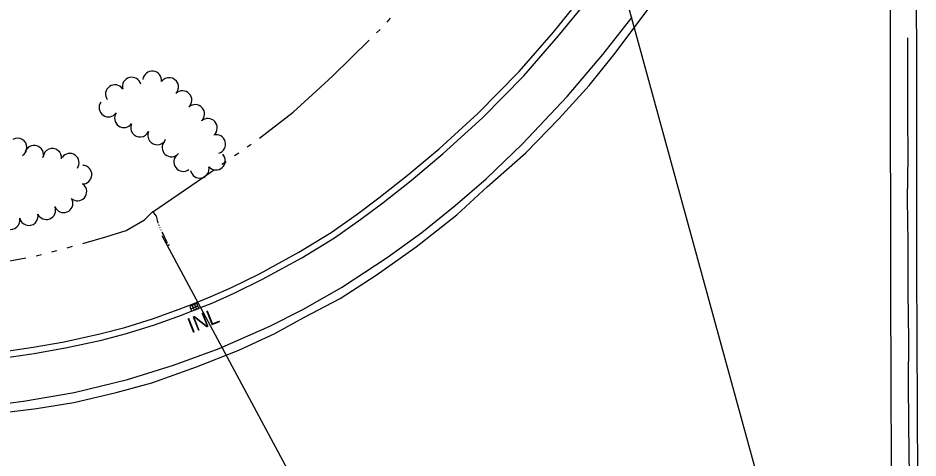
# Model space of a CAD drawing. Extents: x 589250 to 1188077, y 162953 to 363065.
# Drawn here: x 593646.2 to 594001.4, y 174071.1 to 174244.8 of the extents above; entities that cross this region are included whole.
import ezdxf

# ---------------------------------------------------------------- set-up
doc = ezdxf.new("R2010")
doc.units = 0
for name, color, linetype in [('E_DRN', 7, 'Continuous'), ('E_DRN_Pipe', 7, 'Continuous'), ('E_DRN_SS_UG', 7, 'Continuous'), ('E_DRN_Text', 7, 'Continuous'), ('E_LAND_TreeLine_P', 7, 'Continuous'), ('E_RDWY', 7, 'Continuous'), ('E_RDWY_C_and_G', 7, 'Continuous'), ('E_RDWY_Gravel', 7, 'Continuous'), ('E_WTR_FlowLine', 7, 'Continuous')]:
    doc.layers.add(name, color=color, linetype=linetype)

msp = doc.modelspace()

# ---------------------------------------------------------------- linework, layer by layer
at = {"layer": 'E_DRN'}
for p, q in [((593716.8, 174132.02), (593714.01, 174130.92)), ((593714.01, 174130.92), (593714.75, 174129.06)), ((593714.38, 174129.99), (593717.17, 174131.1)), ((593714.75, 174129.06), (593717.54, 174130.17)), ((593714.94, 174131.29), (593715.68, 174129.43)), ((593715.87, 174131.66), (593716.61, 174129.8)), ((593717.54, 174130.17), (593716.8, 174132.02))]:
    msp.add_line(p, q, dxfattribs=at)
msp.add_arc((593705.32, 174155.67), 0.688, 244.4487, 350.7089, dxfattribs=at)
at = {"layer": 'E_DRN_Pipe'}
msp.add_lwpolyline([(593997.26, 174236.88), (593997.22, 174205.91), (593997.45, 174190.1), (593997.17, 174173.15), (593997.38, 174156.28), (593997.4, 174136.85), (593997.6, 174117.51), (593997.58, 174100.98), (593997.68, 174084.29), (593997.91, 174063.67), (593997.8, 174044.52), (593998.12, 174021.41), (593998.36, 173997.81), (593998.8, 173968.11)], dxfattribs=at)
at = {"layer": 'E_DRN_SS_UG'}
for p, q in [((593862.64, 174338.2), (593948.9, 174023.91)), ((593702.98, 174158.95), (593820.56, 173940.11))]:
    msp.add_line(p, q, dxfattribs=at)
at = {"layer": 'E_LAND_TreeLine_P'}
for centre, radius, start, end in [((593699.2, 174220.11), 3.7, 353.8888, 173.8888), ((593684.46, 174214.69), 3.7, 35.7089, 215.7089), ((593691.12, 174217.65), 3.7, 15.05, 195.05), ((593705.87, 174217.52), 3.7, 324.1439, 144.1439), ((593711.12, 174212.31), 3.7, 313.7232, 133.7232), ((593681.91, 174209.42), 3.7, 145.4761, 325.4761), ((593716.14, 174206.87), 3.7, 312.3616, 132.3616), ((593688.02, 174205.22), 3.7, 145.4761, 325.4761), ((593721.14, 174201.39), 3.7, 312.3616, 132.3616), ((593694.38, 174201.48), 3.7, 155.5504, 335.5504), ((593646.08, 174193.61), 3.67, 300.2626, 120.2626), ((593701.12, 174198.42), 3.7, 155.5504, 335.5504), ((593724.46, 174195), 3.7, 285.7573, 105.7573), ((593652.57, 174190.77), 3.67, 342.5788, 162.5788), ((593706.79, 174193.69), 3.7, 138.5033, 318.5033), ((593659.79, 174189.57), 3.67, 353.1605, 173.1605), ((593666.66, 174187.64), 3.67, 324.6294, 144.6294), ((593711.41, 174187.93), 3.7, 127.0412, 307.0412), ((593724.32, 174188.48), 3.7, 222.6473, 42.6473), ((593671.68, 174182.92), 3.67, 267.4374, 87.4374), ((593717.95, 174185.27), 3.7, 191.3186, 11.3186), ((593669.68, 174176.28), 3.67, 227.8614, 47.8614), ((593664.22, 174171.61), 3.67, 201.7393, 21.7393), ((593657.4, 174168.89), 3.67, 201.7393, 21.7393), ((593643.29, 174165), 3.67, 192.3237, 12.3237), ((593650.46, 174166.56), 3.67, 192.3237, 12.3237)]:
    msp.add_arc(centre, radius, start, end, dxfattribs=at)
at = {"layer": 'E_RDWY'}
for p, q in [((594000.92, 174228.15), (594000.77, 174260.2)), ((593877.05, 174230.32), (593888.61, 174245.1)), ((593862.96, 174213.71), (593877.05, 174230.32)), ((594000.95, 174202.45), (594000.92, 174228.15)), ((593845.36, 174195.08), (593862.96, 174213.71)), ((594000.93, 174171.67), (594000.95, 174202.45)), ((593831.02, 174181.23), (593845.36, 174195.08)), ((593818.79, 174170.77), (593831.02, 174181.23)), ((593805.59, 174160.09), (593818.79, 174170.77)), ((594000.93, 174171.67), (594000.93, 174171.67)), ((594000.96, 174145.69), (594000.93, 174171.67)), ((593791.97, 174150.2), (593805.59, 174160.09)), ((593773.85, 174138.45), (593791.97, 174150.2)), ((594001.02, 174118.58), (594000.96, 174145.69)), ((593758.64, 174129.71), (593773.85, 174138.45)), ((593745.55, 174123.17), (593758.64, 174129.71)), ((593725.61, 174114.34), (593745.55, 174123.17)), ((594001.23, 174090.48), (594001.02, 174118.58)), ((593707.6, 174107.72), (593725.61, 174114.34)), ((593689.38, 174102.08), (593707.6, 174107.72)), ((593668.39, 174096.98), (593689.38, 174102.08)), ((593648.35, 174093.47), (593668.39, 174096.98)), ((593632.23, 174091.41), (593648.35, 174093.47)), ((594001.4, 174057.16), (594001.23, 174090.48))]:
    msp.add_line(p, q, dxfattribs=at)
at = {"layer": 'E_RDWY_C_and_G'}
for p, q in [((593857.54, 174239.14), (593869.07, 174253.43)), ((593859.45, 174237.53), (593871.05, 174251.9)), ((593843.98, 174223.66), (593857.54, 174239.14)), ((593845.81, 174221.96), (593859.45, 174237.53)), ((593827.75, 174207.1), (593843.98, 174223.66)), ((593829.48, 174205.3), (593845.81, 174221.96)), ((593812.37, 174193.13), (593827.75, 174207.1)), ((593814.02, 174191.24), (593829.48, 174205.3)), ((593799.75, 174182.53), (593812.37, 174193.13)), ((593801.33, 174180.59), (593814.02, 174191.24)), ((593788.64, 174173.75), (593799.75, 174182.53)), ((593790.16, 174171.77), (593801.33, 174180.59)), ((593780.04, 174167.33), (593788.64, 174173.75)), ((593781.51, 174165.3), (593790.16, 174171.77)), ((593769.8, 174160.1), (593780.04, 174167.33)), ((593771.17, 174158.01), (593781.51, 174165.3)), ((593757, 174152.32), (593769.8, 174160.1)), ((593758.25, 174150.15), (593771.17, 174158.01)), ((593741.52, 174143.85), (593757, 174152.32)), ((593742.68, 174141.63), (593758.25, 174150.15)), ((593730.48, 174138.4), (593741.52, 174143.85)), ((593731.54, 174136.14), (593742.68, 174141.63)), ((593722.09, 174134.67), (593730.48, 174138.4)), ((593715.35, 174131.99), (593722.09, 174134.67)), ((593723.06, 174132.36), (593731.54, 174136.14)), ((593699.32, 174126.07), (593709.88, 174129.84)), ((593709.88, 174129.84), (593715.35, 174131.99)), ((593710.76, 174127.5), (593716.27, 174129.66)), ((593716.27, 174129.66), (593723.06, 174132.36)), ((593688.37, 174122.67), (593699.32, 174126.07)), ((593700.11, 174123.69), (593710.76, 174127.5)), ((593678.55, 174120.06), (593688.37, 174122.67)), ((593689.06, 174120.27), (593700.11, 174123.69)), ((593664.39, 174117), (593678.55, 174120.06)), ((593679.14, 174117.63), (593689.06, 174120.27)), ((593652.26, 174114.85), (593664.39, 174117)), ((593664.92, 174114.55), (593679.14, 174117.63)), ((593635.39, 174112.42), (593652.26, 174114.85)), ((593635.64, 174109.93), (593652.65, 174112.39)), ((593652.65, 174112.39), (593664.82, 174114.53))]:
    msp.add_line(p, q, dxfattribs=at)
at = {"layer": 'E_RDWY_Gravel'}
for p, q in [((593990.44, 174268.25), (593990.36, 174238.32)), ((593881.37, 174230.28), (593894.9, 174248.23)), ((593990.36, 174238.32), (593990.47, 174197.6)), ((593871.61, 174218.1), (593881.37, 174230.28)), ((593859.83, 174205.06), (593871.61, 174218.1)), ((593846.63, 174191.59), (593859.83, 174205.06)), ((593990.47, 174197.6), (593990.56, 174169.51)), ((593831.39, 174178.09), (593846.63, 174191.59)), ((593819.37, 174167.09), (593831.39, 174178.09)), ((593990.56, 174169.51), (593990.58, 174133.67)), ((593803.31, 174154.38), (593819.37, 174167.09)), ((593787.62, 174143.31), (593803.31, 174154.38)), ((593773.33, 174134.1), (593787.62, 174143.31)), ((593759.01, 174126.52), (593773.33, 174134.1)), ((593990.58, 174133.67), (593990.69, 174104.56)), ((593747.52, 174120.21), (593759.01, 174126.52)), ((593733.38, 174113.65), (593747.52, 174120.21)), ((593716.6, 174107.04), (593733.38, 174113.65)), ((593698.99, 174100.82), (593716.6, 174107.04)), ((593990.69, 174104.56), (593990.78, 174064.65)), ((593685.02, 174096.91), (593698.99, 174100.82)), ((593668.19, 174092.95), (593685.02, 174096.91)), ((593639.75, 174088.98), (593653.57, 174090.65)), ((593653.57, 174090.65), (593668.19, 174092.95))]:
    msp.add_line(p, q, dxfattribs=at)
at = {"layer": 'E_WTR_FlowLine'}
for p, q in [((593791.89, 174243.17), (593793.25, 174244.64)), ((593787.69, 174238.87), (593789.12, 174240.27)), ((593770.4, 174221.91), (593784.83, 174236.06)), ((593763.87, 174215.91), (593770.4, 174221.91)), ((593754.76, 174207.55), (593763.87, 174215.91)), ((593741.53, 174197.34), (593754.76, 174207.55)), ((593736.61, 174193.88), (593738.26, 174195.02)), ((593731.66, 174190.46), (593733.31, 174191.6)), ((593726.72, 174187.03), (593728.37, 174188.17)), ((593719.45, 174182), (593723.42, 174184.75)), ((593699.46, 174168.28), (593719.45, 174182)), ((593688.85, 174160.9), (593696.08, 174165.15)), ((593696.08, 174165.15), (593699.49, 174168.33)), ((593700.92, 174166.48), (593699.49, 174168.33)), ((593701.26, 174164.93), (593700.92, 174166.48)), ((593701.58, 174163.75), (593701.26, 174164.93)), ((593701.76, 174163.06), (593701.76, 174163.06)), ((593701.92, 174162.75), (593701.76, 174163.06)), ((593702.38, 174161.82), (593702.23, 174162.13)), ((593671.74, 174155.78), (593680.85, 174158.33)), ((593680.85, 174158.33), (593688.85, 174160.9)), ((593702.85, 174160.88), (593702.7, 174161.2)), ((593703.54, 174159.51), (593703.16, 174160.26)), ((593705.17, 174155.79), (593703.54, 174159.51)), ((593665.67, 174154.08), (593667.69, 174154.64)), ((593653.44, 174150.95), (593655.48, 174151.46)), ((593659.56, 174152.49), (593661.6, 174153)), ((593636.86, 174147.81), (593649.31, 174150.16))]:
    msp.add_line(p, q, dxfattribs=at)

# ---------------------------------------------------------------- texts
at = {"layer": 'E_DRN_Text'}
msp.add_text('INL', height=6, rotation=21.6601, dxfattribs=at).set_placement((593714.61, 174120.25))

doc.saveas('drawing.dxf')
